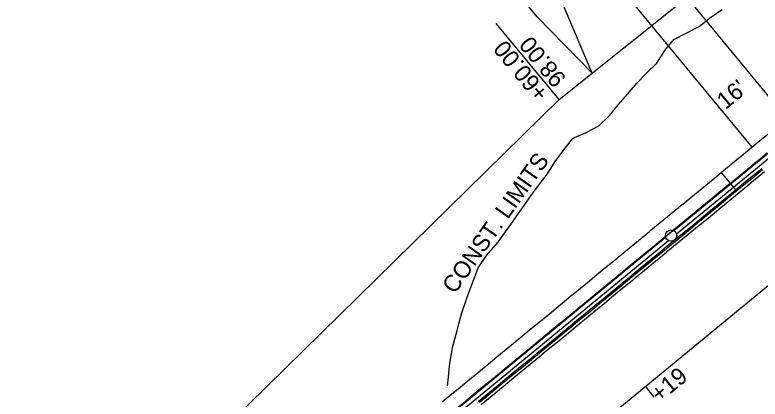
# Model space of a CAD drawing. Extents: x 1147550 to 1149124, y 2017436 to 2018779.
# Drawn here: x 1148642.9 to 1148907, y 2018467.3 to 2018603.7 of the extents above; entities that cross this region are included whole.
import ezdxf

# ---------------------------------------------------------------- set-up
doc = ezdxf.new("R2010")
doc.units = 0
for name, color, linetype in [('S_EDGE_CONCRETE', 7, 'Continuous'), ('S_ELECTRIC_UTILITIES', 7, 'Continuous'), ('S_HEADWALL', 7, 'Continuous'), ('S_IRON_PIN', 7, 'Continuous'), ('S_LANDSCAPING', 7, 'Continuous'), ('S_MAILBOX', 7, 'Continuous'), ('S_SECONDARY_CTL', 7, 'Continuous'), ('S_TELEPHONE_UTILITIES', 7, 'Continuous'), ('S_TELEPHONE_UTILITIES_ANNOT', 7, 'Continuous')]:
    doc.layers.add(name, color=color, linetype=linetype)

msp = doc.modelspace()

# ---------------------------------------------------------------- linework, layer by layer
at = {"layer": 'S_EDGE_CONCRETE'}
msp.add_line((1148677.53, 2018316.54), (1149083.36, 2018650.43), dxfattribs=at)
at = {"layer": 'S_ELECTRIC_UTILITIES'}
msp.add_lwpolyline([(1148835.76, 2018573.62), (1148813.52, 2018600.65)], dxfattribs=at)
at = {"layer": 'S_HEADWALL'}
for p, q in [((1148837.98, 2018662.21), (1148916.45, 2018566.84)), ((1148825.63, 2018652.05), (1148904.09, 2018556.68)), ((1148893.28, 2018547.78), (1148898.36, 2018541.6)), ((1148869.54, 2018468.03), (1148866.36, 2018471.9))]:
    msp.add_line(p, q, dxfattribs=at)
at = {"layer": 'S_IRON_PIN'}
msp.add_lwpolyline([(1148847.47, 2018583), (1148820.22, 2018647.6), (1148843.39, 2018666.66), (1148902.12, 2018626.75)], dxfattribs=at)
at = {"layer": 'S_LANDSCAPING'}
msp.add_lwpolyline([(1148847.47, 2018583), (1148827.96, 2018602.98), (1148805.73, 2018630.01)], dxfattribs=at)
at = {"layer": 'S_MAILBOX'}
msp.add_line((1148835.76, 2018573.62), (1149023.13, 2018723.63), dxfattribs=at)
msp.add_lwpolyline([(1147550.1, 2017525.89), (1147894.72, 2017801.4), (1147903.55, 2017831.14), (1148035.64, 2017933.4), (1148261.5, 2018084.85), (1148285.74, 2018084.65), (1148479.1, 2018223.18), (1148835.76, 2018573.62)], dxfattribs=at)
at = {"layer": 'S_SECONDARY_CTL'}
msp.add_lwpolyline([(1148796.26, 2018472.11), (1148796.55, 2018475.14), (1148796.95, 2018479.14), (1148798.02, 2018485.71), (1148799.6, 2018491.65), (1148800.25, 2018494.08), (1148801.19, 2018497.6), (1148803.09, 2018503.16), (1148805.12, 2018508.56), (1148805.81, 2018510.4), (1148807.15, 2018513.96), (1148810.08, 2018518.26), (1148813.39, 2018522.11), (1148814.21, 2018523.07), (1148816.48, 2018526.23), (1148818.87, 2018529.62), (1148819.47, 2018530.46), (1148822.45, 2018534.71), (1148823.17, 2018535.73), (1148825.44, 2018538.95), (1148828.43, 2018543.18), (1148831.6, 2018547.2), (1148832, 2018547.82), (1148834.43, 2018551.63), (1148837.44, 2018555.84), (1148840.6, 2018559.87), (1148841.23, 2018560.19), (1148845.38, 2018561.93), (1148849.92, 2018564.28), (1148853.48, 2018567.83), (1148853.67, 2018568.02), (1148856.7, 2018571.78), (1148860.06, 2018575.57), (1148863.37, 2018579.41), (1148863.37, 2018579.41), (1148866.85, 2018583.06), (1148870.4, 2018586.6), (1148873.23, 2018590.99), (1148873.24, 2018591.02), (1148876.49, 2018594.95), (1148881.04, 2018597.29), (1148885.41, 2018599.59), (1148885.55, 2018599.67), (1148889.45, 2018602.8), (1148893.62, 2018605.6)], dxfattribs=at)
at = {"layer": 'S_TELEPHONE_UTILITIES'}
msp.add_line((1148654.34, 2018344.72), (1148896.46, 2018543.92), dxfattribs=at)
for points in [[(1148794.43, 2018466.46), (1148798.29, 2018469.63), (1148799.96, 2018471), (1148802.16, 2018472.81), (1148806.02, 2018475.99), (1148809.88, 2018479.16), (1148811.45, 2018480.46), (1148813.74, 2018482.34), (1148817.6, 2018485.52), (1148821.46, 2018488.69), (1148822.78, 2018489.78), (1148825.32, 2018491.87), (1148829.18, 2018495.05), (1148833.05, 2018498.22), (1148834, 2018499.01), (1148836.91, 2018501.4), (1148840, 2018503.94), (1148840.77, 2018504.58), (1148844.63, 2018507.75), (1148845.56, 2018508.52), (1148848.49, 2018510.93), (1148852.35, 2018514.11), (1148856.21, 2018517.29), (1148856.76, 2018517.74), (1148860.07, 2018520.46), (1148863.93, 2018523.64), (1148867.8, 2018526.82), (1148868.33, 2018527.25), (1148871.66, 2018529.99), (1148875.52, 2018533.17), (1148879.38, 2018536.35), (1148879.59, 2018536.52), (1148883.24, 2018539.52), (1148887.1, 2018542.7), (1148890.96, 2018545.87), (1148890.96, 2018545.88), (1148894.82, 2018549.05), (1148898.69, 2018552.23), (1148902.52, 2018555.38), (1148902.55, 2018555.41), (1148906.41, 2018558.58), (1148910.27, 2018561.76)], [(1148803.13, 2018467.14), (1148805.33, 2018468.95), (1148809.19, 2018472.13), (1148813.06, 2018475.3), (1148814.63, 2018476.6), (1148816.92, 2018478.48), (1148820.78, 2018481.66), (1148824.64, 2018484.83), (1148825.96, 2018485.92), (1148828.5, 2018488.01), (1148832.36, 2018491.19), (1148836.22, 2018494.36), (1148837.18, 2018495.15), (1148840.08, 2018497.54), (1148843.17, 2018500.08), (1148843.94, 2018500.72), (1148847.81, 2018503.89), (1148848.73, 2018504.66), (1148851.67, 2018507.07), (1148855.53, 2018510.25), (1148859.39, 2018513.42), (1148859.94, 2018513.87), (1148863.25, 2018516.6), (1148867.11, 2018519.78), (1148870.97, 2018522.95), (1148871.51, 2018523.39), (1148874.83, 2018526.13), (1148878.69, 2018529.31), (1148882.56, 2018532.48), (1148882.77, 2018532.66), (1148886.42, 2018535.66), (1148890.28, 2018538.84), (1148894.14, 2018542.01), (1148894.14, 2018542.01), (1148898, 2018545.19), (1148901.86, 2018548.37), (1148905.7, 2018551.52), (1148905.72, 2018551.54), (1148909.58, 2018554.72)], [(1148807.24, 2018466.63), (1148811.1, 2018469.81), (1148814.96, 2018472.99), (1148816.54, 2018474.28), (1148818.82, 2018476.16), (1148822.68, 2018479.34), (1148826.54, 2018482.52), (1148827.86, 2018483.6), (1148830.41, 2018485.69), (1148834.27, 2018488.87), (1148838.13, 2018492.05), (1148839.09, 2018492.84), (1148841.99, 2018495.22), (1148845.08, 2018497.77), (1148845.85, 2018498.4), (1148849.71, 2018501.58), (1148850.64, 2018502.34), (1148853.57, 2018504.75), (1148857.43, 2018507.93), (1148861.3, 2018511.11), (1148861.84, 2018511.56), (1148865.16, 2018514.28), (1148869.02, 2018517.46), (1148872.88, 2018520.64), (1148873.41, 2018521.08), (1148876.74, 2018523.81), (1148880.6, 2018526.99), (1148884.46, 2018530.17), (1148884.68, 2018530.34), (1148888.32, 2018533.34), (1148892.18, 2018536.52), (1148896.04, 2018539.7), (1148896.05, 2018539.7), (1148899.91, 2018542.87), (1148903.77, 2018546.05), (1148907.6, 2018549.21)], [(1148807.56, 2018466.25), (1148811.42, 2018469.42), (1148815.28, 2018472.6), (1148816.85, 2018473.9), (1148819.14, 2018475.78), (1148823, 2018478.95), (1148826.86, 2018482.13), (1148828.18, 2018483.21), (1148830.72, 2018485.31), (1148834.58, 2018488.48), (1148838.45, 2018491.66), (1148839.4, 2018492.45), (1148842.31, 2018494.84), (1148845.4, 2018497.38), (1148846.17, 2018498.01), (1148850.03, 2018501.19), (1148850.96, 2018501.95), (1148853.89, 2018504.37), (1148857.75, 2018507.54), (1148861.61, 2018510.72), (1148862.16, 2018511.17), (1148865.47, 2018513.9), (1148869.34, 2018517.07), (1148873.2, 2018520.25), (1148873.73, 2018520.69), (1148877.06, 2018523.43), (1148880.92, 2018526.6), (1148884.78, 2018529.78), (1148884.99, 2018529.96), (1148888.64, 2018532.96), (1148892.5, 2018536.13), (1148896.36, 2018539.31), (1148896.36, 2018539.31), (1148900.22, 2018542.49), (1148904.09, 2018545.66), (1148907.92, 2018548.82)], [(1148808.19, 2018465.47), (1148812.05, 2018468.65), (1148815.91, 2018471.83), (1148817.49, 2018473.12), (1148819.78, 2018475.01), (1148823.64, 2018478.18), (1148827.5, 2018481.36), (1148828.81, 2018482.44), (1148831.36, 2018484.54), (1148835.22, 2018487.71), (1148839.08, 2018490.89), (1148840.04, 2018491.68), (1148842.94, 2018494.07), (1148846.03, 2018496.61), (1148846.8, 2018497.24), (1148850.66, 2018500.42), (1148851.59, 2018501.18), (1148854.53, 2018503.6), (1148858.39, 2018506.77), (1148862.25, 2018509.95), (1148862.8, 2018510.4), (1148866.11, 2018513.13), (1148869.97, 2018516.3), (1148873.83, 2018519.48), (1148874.37, 2018519.92), (1148877.69, 2018522.66), (1148881.55, 2018525.83), (1148885.41, 2018529.01), (1148885.63, 2018529.19), (1148889.28, 2018532.19), (1148893.14, 2018535.36), (1148897, 2018538.54), (1148897, 2018538.54), (1148900.86, 2018541.72), (1148904.72, 2018544.89), (1148908.55, 2018548.05)]]:
    msp.add_lwpolyline(points, dxfattribs=at)
at = {"layer": 'S_TELEPHONE_UTILITIES_ANNOT'}
for p, q in [((1148876.42, 2018527.12), (1149060.33, 2018678.42)), ((1148876.42, 2018527.12), (1149060.33, 2018678.42)), ((1148877.38, 2018525.96), (1149061.28, 2018677.26)), ((1148877.38, 2018525.96), (1149061.28, 2018677.26)), ((1148644.81, 2018336.58), (1148873.56, 2018524.76)), ((1148644.81, 2018336.58), (1148873.56, 2018524.76)), ((1148645.77, 2018335.43), (1148874.51, 2018523.6)), ((1148645.77, 2018335.43), (1148874.51, 2018523.6))]:
    msp.add_line(p, q, dxfattribs=at)
msp.add_circle((1148875.47, 2018525.36), 2, dxfattribs=at)

# ---------------------------------------------------------------- texts
at = {"layer": 'S_ELECTRIC_UTILITIES'}
for s, p in [('+60.00', (1148832.45, 2018576.08)), ('98.00', (1148838.62, 2018581.16))]:
    msp.add_text(s, height=6, rotation=129.4453, dxfattribs=at).set_placement(p)
at = {"layer": 'S_HEADWALL'}
for s, p in [("16'", (1148894.78, 2018569.88)), ('+19', (1148871.32, 2018465.87))]:
    msp.add_text(s, height=6, rotation=39.4453, dxfattribs=at).set_placement(p)
at = {"layer": 'S_SECONDARY_CTL'}
msp.add_text('CONST. LIMITS', height=6, rotation=54.7466, dxfattribs=at).set_placement((1148798.79, 2018504.32))

doc.saveas('drawing.dxf')
